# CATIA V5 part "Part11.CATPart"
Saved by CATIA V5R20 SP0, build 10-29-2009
Part number: Part11
Bounding box of the stored display mesh (mm): x -300 to 300, y -300 to 300, z -300 to 300
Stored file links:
  E:\新建文件夹 (2)\Part11.CATPart
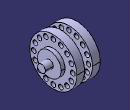
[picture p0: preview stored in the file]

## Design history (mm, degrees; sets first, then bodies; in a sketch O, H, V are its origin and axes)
Body1 (main body)
  Sketch1 on yz-plane, origin (0, 0, 0), H (0, 1, 0), V (0, 0, 1)
    circle A1 centre (0, 0) radius 300
    circle A2 centre (0, 0) radius 50
    point P1 (0, 50)
    point P2 (0, 250)
    circle A3 centre (0, 250) radius 30
    point P3 (0, 220)
    circle A4 centre (0, -250) radius 30
    point P4 (0, -250)
    point P5 (0, -280)
    circle A5 centre (176.7767, 176.7767) radius 30
    point P7 (197.9899, 197.9899)
    circle A6 centre (250, 0) radius 30
    point P8 (250, 0)
    point P9 (220, 0)
    circle A7 centre (-250, 0) radius 30
    point P10 (-250, 0)
    point P11 (-220, 0)
    circle A8 centre (-176.7767, -176.7767) radius 30
    point P13 (0, 0)
    circle A9 centre (-176.7767, 176.7767) radius 30
    circle A10 centre (176.7767, -176.7767) radius 30
    circle A11 centre (95.6709, 230.9699) radius 30
    circle A12 centre (-95.6709, 230.9699) radius 30
    circle A13 centre (95.6709, -230.9699) radius 30
    circle A14 centre (-95.6709, -230.9699) radius 30
    circle A15 centre (230.9699, 95.6709) radius 30
    circle A16 centre (-230.9699, 95.6709) radius 30
    circle A17 centre (-230.9699, -95.6709) radius 30
    circle A18 centre (230.9699, -95.6709) radius 30
    radius A1 = 300
    coincidence: A2 P1, P1 V, P2 V, A3 P3, P3 V, P4 V, A4 P5, P5 V, A5 P7, P8 H, A6 P9, P9 H, P10 H, A7 P11, P11 H, P13 V
  Pad1: profile Sketch1, direction (1, 0, 0), length 150, mirrored extent
  Body2
    Sketch2 on yz-plane, origin (0, 0, 0), H (0, 1, 0), V (0, 0, 1)
      circle A1 centre (0, 0) radius 300
      point P1 (0, 300)
      circle A2 centre (0, 0) radius 100
      point P2 (0, 100)
      coincidence: A1 P1, P1 V, A2 P2, P2 V
    Pad2: profile Sketch2, direction (1, 0, 0), length 50, mirrored extent
  Remove1: tool Body2
  Sketch3 on yz-plane, origin (0, 0, 0), H (0, 1, 0), V (0, 0, 1)
    circle A1 centre (0, 0) radius 50
    point P1 (0, 50)
    coincidence: A1 P1, P1 V
  Pad3: profile Sketch3, direction (1, 0, 0), length 300, mirrored extent
  Sketch4 on end face of Pad1, origin (150, 0, 0), H (0, 1, 0), V (0, 0, 1)
    circle A1 centre (0, 0) radius 50
    point P1 (0, 50)
    circle A2 centre (0, 0) radius 150
    point P2 (0, 150)
    coincidence: A1 P1, P1 V, A2 P2, P2 V
  Pad4: profile Sketch4, direction (1, 0, 0), length 50
  Sketch5 on start face of Pad1, origin (-150, 0, 0), H (0, -1, 0), V (0, 0, 1)
    circle A1 centre (0, 0) radius 150
    point P1 (0, 150)
    circle A2 centre (0, 0) radius 50
    point P2 (0, 50)
    coincidence: A1 P1, P1 V, A2 P2, P2 V
  Pad5: profile Sketch5, direction (-1, 0, 0), length 50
